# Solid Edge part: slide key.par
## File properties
Title: Slide Key
Author: Abhinav Rai
Template: Normal.par
Last saved by: Robert a Rhodes jr
Revision: 7
Application: Solid Edge
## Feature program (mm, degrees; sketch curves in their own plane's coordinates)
sketch for "unnamed Protrusion 1" plane through (0, 0, 0) normal (0, -1, 0) x-axis (1, 0, 0)
  line (-30.0365, -12.1146) -> (28.6883, -12.1146)
  line (28.6883, -12.1146) -> (28.6883, -17.6629)
  line (1.9812, -17.6629) -> (28.6883, -17.6629)
  line (1.9812, -13.3979) -> (1.9812, -17.6629)
  line (-1.9812, -13.3979) -> (1.9812, -13.3979)
  line (-1.9812, -17.6629) -> (-1.9812, -13.3979)
  line (-30.0365, -17.6629) -> (-1.9812, -17.6629)
  line (-30.0365, -17.6629) -> (-30.0365, -12.1146)
extrude "unnamed Protrusion 1" add finite 4.7244 along +normal
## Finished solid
Body 1: solid body, 10 faces, 24 edges, 16 vertices.
  Faces by surface: plane 10
  Edges by curve: line 24
Bounding box of the edges (mm): 58.725 x 4.724 x 5.548, from (-30.0365, -4.7244, -17.6629) to (28.6883, 0, -12.1146).
Planar faces by outward normal: +x 2, +y 1, +z 1, -x 2, -y 1, -z 3
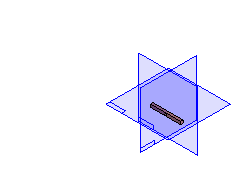
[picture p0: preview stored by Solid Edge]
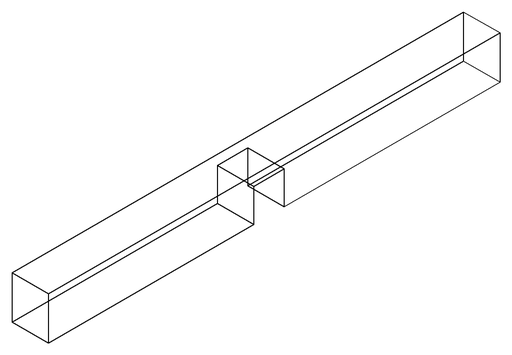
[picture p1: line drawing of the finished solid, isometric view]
